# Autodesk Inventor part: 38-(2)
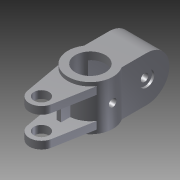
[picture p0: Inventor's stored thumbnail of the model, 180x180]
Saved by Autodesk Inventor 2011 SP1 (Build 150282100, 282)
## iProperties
Created: 2014-02
Part Number: 38-(2)
Document SubType Name: Modeling
Designer: Administrator
Density: 1 g/cm^3
Author: Administrator
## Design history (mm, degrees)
sketch "草图1"
  geometry: C1 r 30 at (0, 0); 1 further point
  constraints: 1 centre point, 1 coincident
  dimensions: "d0" = 60 diameter of C1
extrude "拉伸1" new body sketch "草图1" stored distance "d1" = 60; taper "d2" = 0 deg
hole "Hole1" diameter "d5" = 40; stored, may be unused: countersink angle "d9" = 90 deg, drill point angle "d11" = 118 deg; dims "d3" = 10, "d4" = 10, "d6" = 6, "d7" = 4, "d8" = 2, "d10" = 8
node "工作平面1"
sketch "草图2"
  geometry: L1 (-25, -16.583)-(-15.745, -67.843); L2 (25, -16.583)-(15.745, -67.843); A1 r 30 centre (0, 0) between (-25, -16.583) and (25, -16.583) reference; A2 r 16 centre (0, -65) between (-15.745, -67.843) and (15.745, -67.843); 1 further point
  constraints: 4 end point, 4 point on circle, 2 tangent, 1 centre point, 1 vertical alignment
  dimensions: "d13" = 32 diameter of A2; "d14" = 65 distance of A2.centre point (0, 0)
extrude "拉伸2" join sketch "草图2" distance "d16" = 10; taper "d17" = 0 deg
hole "Hole2" diameter "d20" = 20; stored, may be unused: countersink angle "d24" = 90 deg, drill point angle "d26" = 118 deg; dims "d18" = 10, "d19" = 10, "d21" = 6, "d22" = 4, "d23" = 2, "d25" = 8
mirror "镜像1"
sketch "草图3"
  geometry: L1 (-67.843, -15)-(-16.583, -15) reference; L2 (-67.843, 15)-(-16.583, 15) reference; L3 (-42, -15)-(-42, 15); 1 further point
  constraints: 2 end point, 2 point on line, 1 perpendicular
  dimensions: "d27" = 42 distance from line of point (0, 0) L3
feature "加强筋1" sketch "草图3" dims "d28" = 1, "d29" = 6, "d30" = 0
node "工作平面2"
sketch "草图4"
  geometry: L1 (-30, 30)-(30, 30) reference; L2 (30, -30)-(-30, -30) reference; C1 r 12.5 at (0, 0); 1 further point
  constraints: 1 centre point, 1 coincident
  dimensions: "d32" = 25 diameter of C1
extrude "拉伸3" join sketch "草图4" stored distance "d33" = 10; taper "d34" = 0 deg
hole "Hole3" diameter "d37" = 10; stored, may be unused: countersink angle "d41" = 90 deg, drill point angle "d43" = 118 deg; dims "d35" = 10, "d36" = 10, "d38" = 6, "d39" = 20, "d40" = 4, "d42" = 8
node "工作平面3"
sketch "草图5"
  geometry: 2 further points
  constraints: 1 coincident
hole "Hole4" sketch "草图5" at (0, 0) diameter "d45" = 15; stored, may be unused: countersink angle "d49" = 90 deg, drill point angle "d51" = 0 deg; dims "d46" = 6, "d47" = 20, "d48" = 4, "d50" = 20
sketch "草图6"
  geometry: L1 (25, 16.583)-(25, 50); L2 (-25, 50)-(-25, 16.583); L3 (-25, 50)-(25, 50); A1 r 30 centre (0, 0) between (-25, 16.583) and (25, 16.583) reference; 2 further points
  constraints: 6 end point, 2 point on circle, 1 coincident, 1 parallel, 1 perpendicular
extrude "拉伸4" join sketch "草图6" stored distance "d56" = 60; taper "d57" = 0 deg
node "工作平面4"
sketch "草图9"
  geometry: L1 (-15.612, 12.5)-(15.612, 12.5); L2 (15.612, 12.5)-(15.612, 50); L3 (-15.612, 50)-(-15.612, 12.5); L4 (8, 12.5)-(15.612, 12.5) reference; L5 (-15.612, 50)-(15.612, 50); 3 further points
  constraints: 8 end point, 2 parallel, 1 horizontal, 1 midpoint, 1 perpendicular, 1 vertical alignment, 1 other
sketch "草图10"
  geometry: L1 (50, -30)-(50, 30) reference; L2 (50, -30)-(50, 30) reference; L3 (50, -30)-(50, 30); A1 r 30 centre (50, 0) between (50, -30) and (50, 30); 3 further points
  constraints: 4 end point, 2 point on circle, 1 centre point, 1 collinear
extrude "拉伸5" join sketch "草图10" stored distance "d76" = 50; taper "d77" = 0 deg
extrude "拉伸6" cut sketch "草图9" stored distance "d78" = 40; taper "d79" = 0 deg
sketch "草图11"
  geometry: 2 further points
  constraints: 1 coincident
hole "Hole7" sketch "草图11" at (0, 0) diameter "d80" = 10; stored, may be unused: countersink angle "d84" = 90 deg, drill point angle "d86" = 118 deg; dims "d81" = 6, "d82" = 20, "d83" = 3, "d85" = 40
sketch "草图12"
  geometry: 2 further points
  dimensions: "d87" = 50 distance of point (30, 33.417) point (30, -16.583)
hole "Hole8" sketch "草图12" at (30, 33.417) diameter "d88" = 10; stored, may be unused: countersink angle "d92" = 90 deg, drill point angle "d94" = 118 deg; dims "d89" = 6, "d90" = 20, "d91" = 3, "d93" = 40
sketch "草图13"
  geometry: L1 (50, -20)-(50, 20); A1 r 20 centre (50, 0) between (50, -20) and (50, 20); 1 further point
  constraints: 2 end point, 2 point on circle, 1 centre point, 1 vertical
extrude "拉伸7" cut sketch "草图13" stored distance "d95" = 32; taper "d96" = 0 deg
sketch "草图14"
  geometry: L1 (15.612, 50)-(-15.612, 50) reference; L2 (-5, 27)-(5, 27); L3 (5, 27)-(5, 45); L4 (5, 45)-(-5, 45); L5 (-5, 45)-(-5, 27); A1 r 20 centre (0, 0) between (15.612, 12.5) and (-15.612, 12.5) reference; 1 further point
  constraints: 8 end point, 2 parallel, 1 horizontal, 1 midpoint, 1 perpendicular, 1 vertical alignment
  dimensions: "d97" = 18 distance of L2.end L3.end; "d98" = 10 distance of L2.start L2.end; "d99" = 5 distance between parallel lines of L1 L4
extrude "拉伸8" cut sketch "草图14" stored distance "d100" = 40; taper "d101" = 0 deg
node "实体1"
other parameters: "d12" = 25, "d31" = 8
